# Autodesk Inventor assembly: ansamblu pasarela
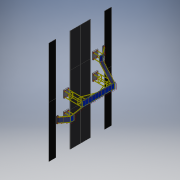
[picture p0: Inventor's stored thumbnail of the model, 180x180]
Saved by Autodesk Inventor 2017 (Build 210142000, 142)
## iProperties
Created: 2017-11
Part Number: ansamblu pasarela
Document SubType Name: Assembly
Designer: iusti
Author: iusti
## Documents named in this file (6)
- C:\Users\iusti\Desktop\pasarela\ansamblu pasarela.iam
- C:\Users\iusti\Desktop\pasarela\beton_suport.ipt
- C:\Users\iusti\Desktop\pasarela\drum.ipt
- C:\Users\iusti\Desktop\pasarela\Schelet pasarela.iam
- C:\Users\iusti\Desktop\pasarela\scara beton.ipt
- C:\Users\iusti\Desktop\pasarela\trotuar.ipt
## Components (14 placed, 5 different names)
1. beton_suport:1 — Mate:1, Flush:1, Flush:2, Flush:3, Flush:5, Flush:6, Flush:13, Flush:14, Mate:8
2. drum:1 — Mate:1, Flush:1, Flush:2, Mate:2, Flush:4, Mate:4, Flush:7, Flush:8, Flush:9, Mate:5, Flush:10
3. beton_suport:2 — Flush:3, Mate:2, Flush:4, Mate:6, Flush:11
4. Schelet pasarela:1 [sub-assembly] — Flush:5, Flush:6, Mate:6, Mate:7, Flush:12, Mate:9, Flush:15, Flush:16, Mate:12, Flush:21, Flush:22
5. drum:2 — Mate:4, Flush:7, Flush:8
6. drum:3 — Flush:9, Mate:5, Flush:10, Flush:17, Flush:18
7. beton_suport:3 — Mate:7, Flush:11, Flush:12
8. beton_suport:4 — Flush:13, Flush:14, Mate:8
9. scara beton:1 — Mate:9, Flush:15, Flush:16, Mate:10
10. trotuar:1 — Flush:17, Mate:10, Flush:18, Mate:11, Flush:19, Flush:20, Flush:25, Flush:26
11. trotuar:2 — Mate:11, Flush:19, Flush:20
12. scara beton:2 — Mate:12, Flush:21, Flush:22, Mate:13
13. trotuar:3 — Mate:13, Mate:14, Flush:23, Flush:24, Flush:25
14. trotuar:4 — Mate:14, Flush:23, Flush:24, Flush:26
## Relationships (39: Flush 26, Mate 13)
- Mate:1: beton_suport:1 ↔ drum:1
- Flush:1: beton_suport:1 ↔ drum:1
- Flush:2: beton_suport:1 ↔ drum:1
- Flush:3: beton_suport:1 ↔ beton_suport:2
- Mate:2: drum:1 ↔ beton_suport:2
- Flush:4: drum:1 ↔ beton_suport:2
- Flush:5: beton_suport:1 ↔ Schelet pasarela:1
- Flush:6: beton_suport:1 ↔ Schelet pasarela:1
- Mate:4: drum:1 ↔ drum:2
- Flush:7: drum:1 ↔ drum:2
- Flush:8: drum:1 ↔ drum:2
- Flush:9: drum:1 ↔ drum:3
- Mate:5: drum:1 ↔ drum:3
- Flush:10: drum:1 ↔ drum:3
- Mate:6: beton_suport:2 ↔ Schelet pasarela:1
- Mate:7: Schelet pasarela:1 ↔ beton_suport:3
- Flush:11: beton_suport:2 ↔ beton_suport:3
- Flush:12: Schelet pasarela:1 ↔ beton_suport:3
- Flush:13: beton_suport:1 ↔ beton_suport:4
- Flush:14: beton_suport:1 ↔ beton_suport:4
- Mate:8: beton_suport:1 ↔ beton_suport:4
- Mate:9: Schelet pasarela:1 ↔ scara beton:1
- Flush:15: Schelet pasarela:1 ↔ scara beton:1
- Flush:16: Schelet pasarela:1 ↔ scara beton:1
- Flush:17: drum:3 ↔ trotuar:1
- Mate:10: scara beton:1 ↔ trotuar:1
- Flush:18: drum:3 ↔ trotuar:1
- Mate:11: trotuar:1 ↔ trotuar:2
- Flush:19: trotuar:1 ↔ trotuar:2
- Flush:20: trotuar:1 ↔ trotuar:2
- Mate:12: Schelet pasarela:1 ↔ scara beton:2
- Flush:21: Schelet pasarela:1 ↔ scara beton:2
- Flush:22: Schelet pasarela:1 ↔ scara beton:2
- Mate:13: scara beton:2 ↔ trotuar:3
- Mate:14: trotuar:3 ↔ trotuar:4
- Flush:23: trotuar:3 ↔ trotuar:4
- Flush:24: trotuar:3 ↔ trotuar:4
- Flush:25: trotuar:1 ↔ trotuar:3
- Flush:26: trotuar:1 ↔ trotuar:4
